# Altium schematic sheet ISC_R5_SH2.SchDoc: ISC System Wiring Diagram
size B; DrawnBy: Filiberto Clara; Engineer: Filiberto Clara; Organization: LIGO Laboratory; Address1: California Institute of Technology; Address2: Massachusetts Institute of Technology; SheetNumber: 20; SheetTotal: 39
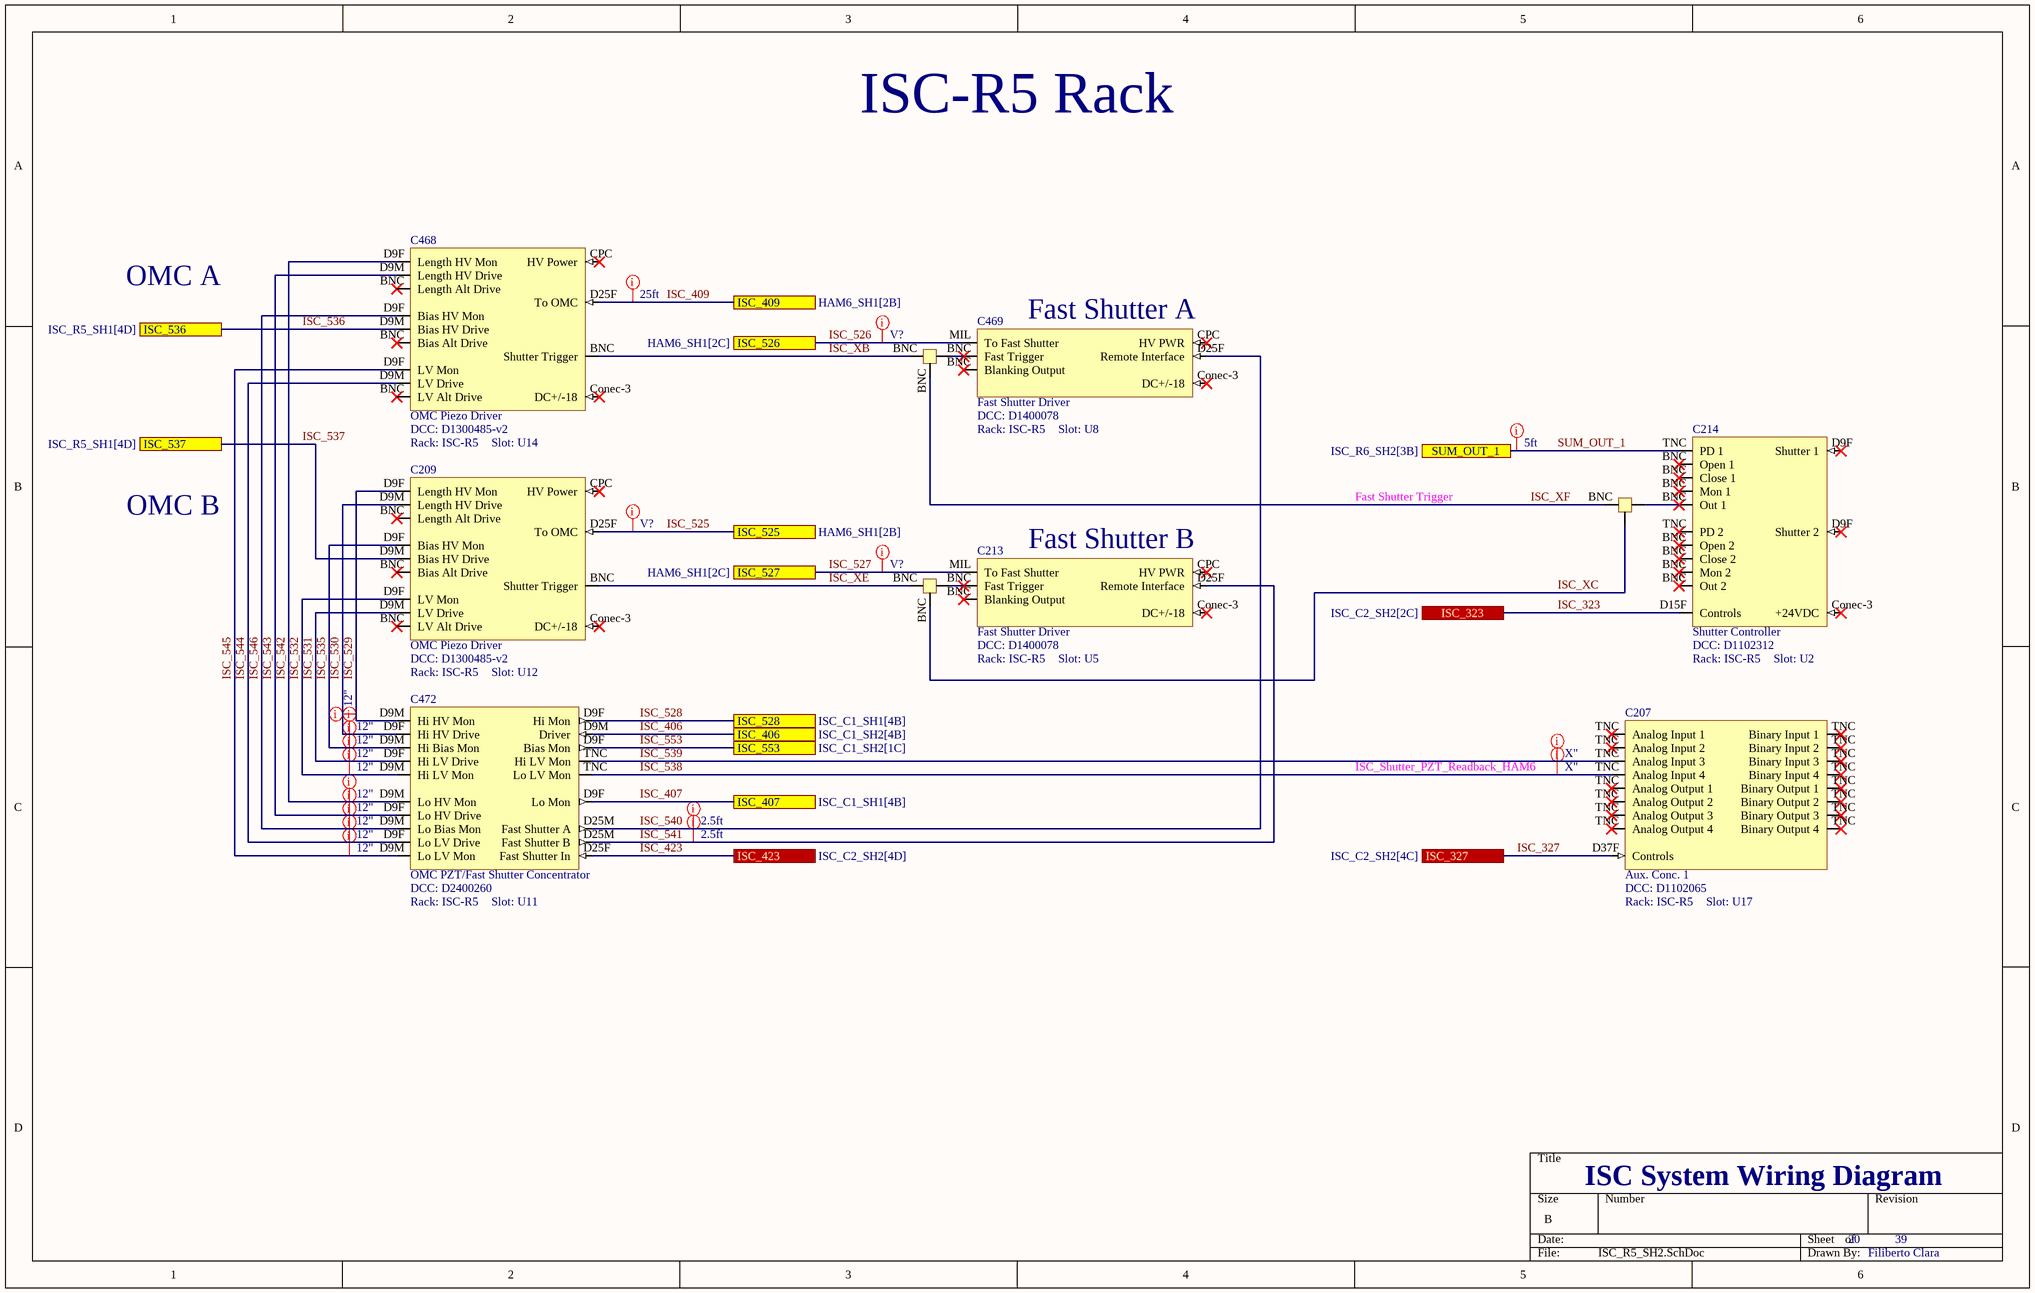
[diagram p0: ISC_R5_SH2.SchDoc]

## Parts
C207  Aux. Conc. 1  DCC: D1102065  Rack: ISC-R5  Slot: U17
C209  OMC Piezo Driver  DCC: D1300485-v2  Rack: ISC-R5  Slot: U12
C213  Fast Shutter Driver  DCC: D1400078  Rack: ISC-R5  Slot: U5
C214  Shutter Controller  DCC: D1102312  Rack: ISC-R5  Slot: U2
C281  Tee  (value not drawn)
C468  OMC Piezo Driver  DCC: D1300485-v2  Rack: ISC-R5  Slot: U14
C469  Fast Shutter Driver  DCC: D1400078  Rack: ISC-R5  Slot: U8
C470  Tee  (value not drawn)
C471  Tee  (value not drawn)
C472  OMC PZT/Fast Shutter Concentrator  DCC: D2400260  Rack: ISC-R5  Slot: U11

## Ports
ISC_323 (see ISC_C2_SH2[2C]), ISC_327 (see ISC_C2_SH2[4C]), ISC_406 (see ISC_C1_SH2[4B]), ISC_407 (see ISC_C1_SH1[4B]), ISC_409 (see HAM6_SH1[2B]), ISC_423 (see ISC_C2_SH2[4D]), ISC_525 (see HAM6_SH1[2B]), ISC_526 (see HAM6_SH1[2C]), ISC_527 (see HAM6_SH1[2C]), ISC_528 (see ISC_C1_SH1[4B]), ISC_536 (see ISC_R5_SH1[4D]), ISC_537 (see ISC_R5_SH1[4D]), ISC_553 (see ISC_C1_SH2[1C]), SUM_OUT_1 (see ISC_R6_SH2[3B])

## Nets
ISC_323: C214.D15F(Controls) ; port ISC_323
ISC_327: C207.D37F(Controls) ; port ISC_327
ISC_406: C472.D9M(Driver) ; port ISC_406
ISC_407: C472.D9F(Lo_Mon) ; port ISC_407
ISC_409: C468.D25F(To_OMC) ; port ISC_409
ISC_423: C472.D25F(Fast_Shutter_In) ; port ISC_423
ISC_525: C209.D25F(To_OMC) ; port ISC_525
ISC_526: C469.MIL(To_Fast_Shutter) ; port ISC_526
ISC_527: C213.MIL(To_Fast_Shutter) ; port ISC_527
ISC_528: C472.D9F(Hi_Mon) ; port ISC_528
ISC_529: C209.D9F(Length_HV_Mon) C472.D9M(Hi_HV_Mon)
ISC_530: C209.D9M(Length_HV_Drive) C472.D9F(Hi_HV_Drive)
ISC_531: C209.D9M(LV_Drive) C472.D9F(Hi_LV_Drive)
ISC_532: C209.D9F(LV_Mon) C472.D9M(Hi_LV_Mon)
ISC_535: C209.D9F(Bias_HV_Mon) C472.D9M(Hi_Bias_Mon)
ISC_536: C468.D9M(Bias_HV_Drive) ; port ISC_536
ISC_537: C209.D9M(Bias_HV_Drive) ; port ISC_537
ISC_538: C207.TNC(Analog_Input_4) C472.TNC(Lo_LV_Mon)
ISC_539: C207.TNC(Analog_Input_1) C472.TNC(Hi_LV_Mon)
ISC_540: C469.D25F(Remote_Interface) C472.D25M(Fast_Shutter_A)
ISC_541: C213.D25F(Remote_Interface) C472.D25M(Fast_Shutter_B)
ISC_542: C468.D9F(Length_HV_Mon) C472.D9M(Lo_HV_Mon)
ISC_543: C468.D9M(Length_HV_Drive) C472.D9F(Lo_HV_Drive)
ISC_544: C468.D9M(LV_Drive) C472.D9F(Lo_LV_Drive)
ISC_545: C468.D9F(LV_Mon) C472.D9M(Lo_LV_Mon)
ISC_546: C468.D9F(Bias_HV_Mon) C472.D9M(Lo_Bias_Mon)
ISC_553: C472.D9F(Bias_Mon) ; port ISC_553
ISC_XB: C468.BNC(Length_Alt_Drive) C470.BNC
ISC_XC: C281.BNC C471.BNC
ISC_XE: C209.BNC(Length_Alt_Drive) C281.BNC
ISC_XF: C470.BNC C471.BNC
SUM_OUT_1: C214.TNC(PD_1) ; port SUM_OUT_1
NetC213_BNC: C213.BNC(Fast_Trigger) C281.BNC
NetC214_BNC: C214.BNC(Open_1) C471.BNC
NetC469_BNC: C469.BNC(Fast_Trigger) C470.BNC

Not connected (* = marked no-connect by the designer): C209 Conec-3(DC+/-18)* CPC(HV_Power)*; C213 Conec-3(DC+/-18)* CPC(HV_PWR)*; C214 Conec-3(+24VDC)* D9F(Shutter_1)*; C468 Conec-3(DC+/-18)* CPC(HV_Power)*; C469 Conec-3(DC+/-18)* CPC(HV_PWR)*

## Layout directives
Length: X": ISC_538, ISC_539
Length: 5ft: SUM_OUT_1
Length: 12": ISC_529, ISC_530, ISC_531, ISC_532, ISC_535, ISC_542, ISC_543, ISC_544, ISC_545, ISC_546
Length: 25ft: ISC_409
Length: V?: ISC_525, ISC_526, ISC_527
Length: 2.5ft: ISC_540, ISC_541

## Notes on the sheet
- ISC-R5 Rack
- OMC A
- (near C469) Fast Shutter A
- OMC B
- Fast Shutter Trigger
- (near C213) Fast Shutter B
- ISC_Shutter_PZT_Readback_HAM6

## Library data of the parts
C207 = Aux. Conc. 1: Serial: Sxxxxxxx; System: ISC
C209 C468 = OMC Piezo Driver V2: Serial: Sxxxxxxx; System: ISC
C213 C469 = Fast Shutter Driver: Serial: Sxxxxxxx; System: ISC
C214 = Shutter Controller: Serial: Sxxxxxxx; System: ISC
C281 C470 C471 = TNC Tee: Tee (TNC); Serial: Sxxxxxxx; System: ISC; Rack: ISCT?; Slot: U?
C472 = OMC PZT/Fast Shutter Panel: Serial: Sxxxxxxx; System: ISC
